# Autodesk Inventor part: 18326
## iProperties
Created: 2007-10
Part Number: 18326
Material: 3.2315.71 AlMgSi1 F28
Description: Zentrierring (Alu/CR) DN 16 KF
Document SubType Name: Modellieren
Designer: TMT
Manufacturer: Standard
Standards Organization: Custom
Density: 1 g/cm^3
Vendor: LEYBOLD
Author: TMT
Comments: LEYBOLD
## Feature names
1. Extrusion2
2. Bohrung1 [Hole]
3. Umdrehung1 [Revolution]
4. Umdrehung2 [Revolution]
5. Fase1 [Chamfer]
